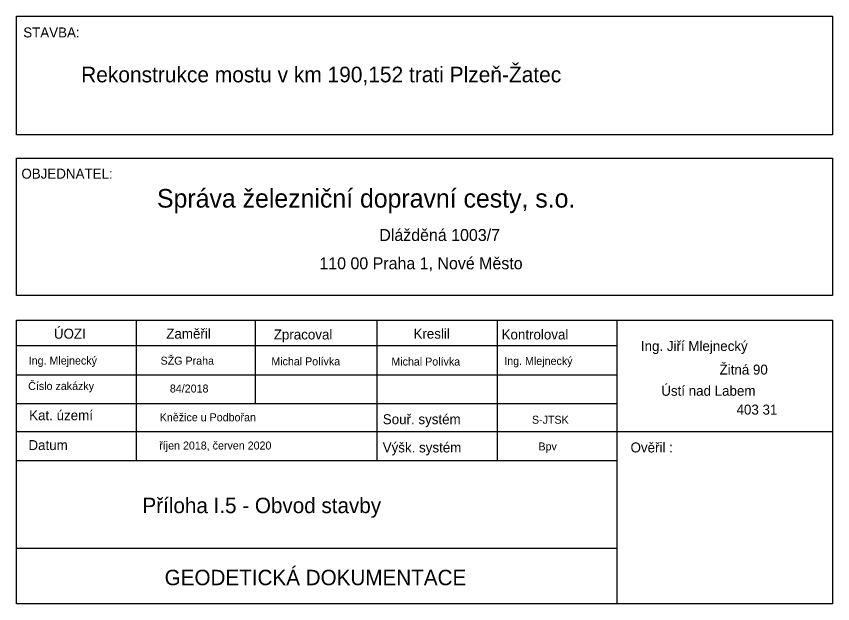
# Model space of a CAD drawing. Extents: x -879530 to -879371, y -1019242 to -1019127.
import ezdxf

# ---------------------------------------------------------------- set-up
doc = ezdxf.new("R2010")
doc.units = 0
doc.layers.add('LEGENDA', color=7, linetype='Continuous')
doc.layers.add('tabulka', color=7, linetype='Continuous')

msp = doc.modelspace()

# ---------------------------------------------------------------- linework, layer by layer
at = {"layer": 'tabulka'}
for p, q in [((-879530.09, -1019186.45), (-879371.44, -1019186.45)), ((-879506.8, -1019186.45), (-879506.8, -1019213.77)), ((-879483.66, -1019186.45), (-879483.66, -1019202.65)), ((-879460.06, -1019186.45), (-879460.06, -1019213.77)), ((-879436.61, -1019186.45), (-879436.61, -1019213.77)), ((-879413.31, -1019241.58), (-879413.31, -1019186.45)), ((-879530.09, -1019191.36), (-879413.31, -1019191.36)), ((-879530.09, -1019197.07), (-879413.31, -1019197.07)), ((-879530.09, -1019202.65), (-879413.31, -1019202.65)), ((-879530.09, -1019208.07), (-879371.44, -1019208.07)), ((-879530.09, -1019213.77), (-879413.31, -1019213.77)), ((-879530.09, -1019230.76), (-879413.31, -1019230.76))]:
    msp.add_line(p, q, dxfattribs=at)
for points in [[(-879530.09, -1019127.36), (-879371.44, -1019127.36), (-879371.44, -1019150.43), (-879530.09, -1019150.43)], [(-879530.09, -1019154.95), (-879371.44, -1019154.95), (-879371.44, -1019181.64), (-879530.09, -1019181.64)]]:
    msp.add_lwpolyline(points, close=True, dxfattribs=at)
msp.add_lwpolyline([(-879371.44, -1019186.45), (-879371.44, -1019241.58), (-879530.09, -1019241.58), (-879530.09, -1019186.45)], dxfattribs=at)

# ---------------------------------------------------------------- texts
at = {"layer": 'LEGENDA'}
msp.add_text('Rekonstrukce mostu v km 190,152 trati Plzeň-Žatec', height=3.04, dxfattribs=at).set_placement((-879517.5, -1019140.2))
at = {"layer": 'tabulka'}
for s, height, p in [('STAVBA:', 1.94, (-879528.75, -1019131.47)), ('OBJEDNATEL:', 1.94, (-879529.1, -1019158.93)), ('Správa železniční dopravní cesty, s.o.', 3.61, (-879502.75, -1019164.56)), ('Dlážděná 1003/7', 2.32, (-879459.55, -1019171.05)), ('110 00 Praha 1, Nové Město', 2.32, (-879471.19, -1019176.55)), ('ÚOZI', 1.94, (-879522.79, -1019190.05)), ('Zaměřil', 1.94, (-879500.95, -1019190.05)), ('Zpracoval', 1.94, (-879480.06, -1019190.2)), ('Kreslil', 1.94, (-879452.9, -1019190.05)), ('Kontroloval', 1.94, (-879435.78, -1019190.2)), ('Ing. Jiří Mlejnecký', 1.94, (-879408.71, -1019192.45)), ('Ing. Mlejnecký', 1.552, (-879527.69, -1019195.08)), ('SŽG Praha', 1.552, (-879502.06, -1019195.11)), ('Michal Polívka', 1.552, (-879480.54, -1019195.23)), ('Michal Polívka', 1.552, (-879457.21, -1019195.27)), ('Ing. Mlejnecký', 1.552, (-879435.26, -1019195.15)), ('Žitná 90', 1.94, (-879393.42, -1019197.03)), ('Číslo zakázky', 1.552, (-879527.79, -1019200.03)), ('84/2018', 1.552, (-879500.25, -1019200.52)), ('Ústí nad Labem', 1.94, (-879404.75, -1019201.15)), ('403 31', 1.94, (-879390.12, -1019204.81)), ('Kat. území', 1.94, (-879527.6, -1019205.91)), ('Kněžice u Podbořan', 1.552, (-879502.22, -1019206.11)), ('Souř. systém', 1.94, (-879458.87, -1019206.68)), ('S-JTSK', 1.552, (-879429.88, -1019206.59)), ('Datum', 1.94, (-879527.74, -1019211.71)), ('říjen 2018, červen 2020', 1.552, (-879502.32, -1019211.6)), ('Výšk. systém', 1.94, (-879458.89, -1019212.17)), ('Bpv', 1.552, (-879428.62, -1019211.78)), ('Ověřil :', 1.94, (-879410.72, -1019212.17)), ('Příloha I.5 - Obvod stavby', 3, (-879505.58, -1019223.98)), ('GEODETICKÁ DOKUMENTACE ', 3, (-879501.27, -1019237.99))]:
    msp.add_text(s, height=height, dxfattribs=at).set_placement(p)

doc.saveas('drawing.dxf')
